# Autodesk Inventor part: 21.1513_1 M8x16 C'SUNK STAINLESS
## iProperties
Created: 2006-12
Part Number: 21.1513_1 M8x16 C'SUNK STAINLESS
Material: Stainless Steel
Description: Hexagon socket countersunk head cap screws
Document SubType Name: Modeling
Standard: DIN 7991
Designer: Andy Moles
Standards Organization: DIN
Language: en-US
Size Designation: M8x16
Categories: <MemberInstance Version="R10.0.0"><Categories><Category DisplayName="Fasteners" InternalName="e4da775c-781d-43d5-af7c-5136215cf5a6" Mnemonic="FSTN"><Category Di
Mass: 8.50303 g
Surface Area: 8.26631 cm^2
Volume: 1.05235 cm^3
Density: 8.08 g/cm^3
Author: Andy Moles
Revision Number: 1
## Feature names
1. Revolution1
2. Extrusion1
3. Fillet1
4. Chamfer1
